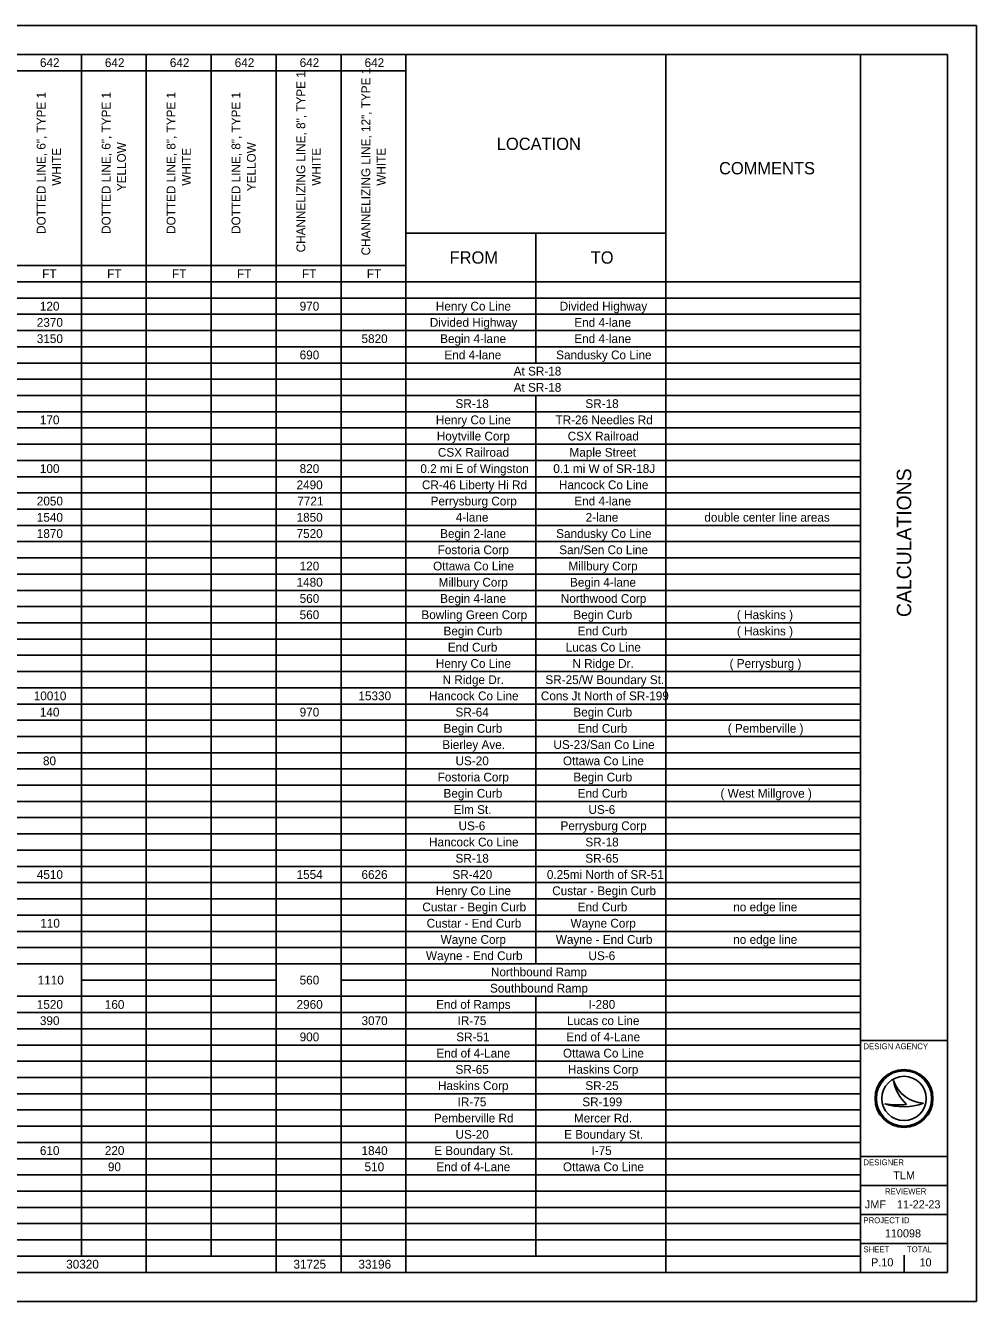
# Model space of a CAD drawing. Extents: x 0 to 34, y 0 to 22.
# Drawn here: x 17.6 to 34, y 0 to 22 of the extents above; entities that cross this region are included whole.
import ezdxf

# ---------------------------------------------------------------- set-up
doc = ezdxf.new("R2010")
doc.units = 0
for name, color, linetype in [('Default', 7, 'Continuous'), ('SH_Border', 7, 'Continuous'), ('SH_Cut_Line', 7, 'Continuous'), ('SH_Data', 7, 'Continuous')]:
    doc.layers.add(name, color=color, linetype=linetype)

msp = doc.modelspace()

# ---------------------------------------------------------------- linework, layer by layer
at = {"layer": 'Default'}
for p, q in [((1.5, 21.5), (32, 21.5)), ((18.562, 21.5), (18.562, 0.782)), ((19.681, 21.5), (19.681, 0.502)), ((20.801, 21.5), (20.801, 0.782)), ((21.921, 21.5), (21.921, 0.502)), ((23.041, 21.5), (23.041, 0.502)), ((24.161, 21.5), (24.161, 0.502)), ((28.64, 21.5), (28.64, 0.502)), ((32, 21.5), (32, 0.502)), ((8.483, 21.22), (24.161, 21.22)), ((24.161, 18.42), (28.64, 18.42)), ((26.401, 18.42), (26.401, 16.181)), ((8.483, 17.86), (24.161, 17.86)), ((1.5, 17.58), (32, 17.58)), ((2.505, 17.3), (32, 17.3)), ((2.505, 17.021), (32, 17.021)), ((2.505, 16.741), (32, 16.741)), ((2.505, 16.461), (32, 16.461)), ((2.505, 16.181), (32, 16.181)), ((2.505, 15.901), (32, 15.901)), ((2.505, 15.621), (32, 15.621)), ((26.401, 15.621), (26.401, 5.822)), ((2.505, 15.341), (32, 15.341)), ((2.505, 15.061), (32, 15.061)), ((2.505, 14.781), (32, 14.781)), ((2.505, 14.501), (32, 14.501)), ((2.505, 14.221), (32, 14.221)), ((2.505, 13.941), (32, 13.941)), ((2.505, 13.661), (32, 13.661)), ((2.505, 13.381), (32, 13.381)), ((2.505, 13.101), (32, 13.101)), ((2.505, 12.821), (32, 12.821)), ((2.505, 12.541), (32, 12.541)), ((2.505, 12.261), (32, 12.261)), ((2.505, 11.981), (32, 11.981)), ((2.505, 11.701), (32, 11.701)), ((2.505, 11.421), (32, 11.421)), ((2.505, 11.141), (32, 11.141)), ((2.505, 10.861), (32, 10.861)), ((2.505, 10.581), (32, 10.581)), ((2.505, 10.301), (32, 10.301)), ((2.505, 10.021), (32, 10.021)), ((2.505, 9.741), (32, 9.741)), ((2.505, 9.461), (32, 9.461)), ((2.505, 9.181), (32, 9.181)), ((2.505, 8.901), (32, 8.901)), ((2.505, 8.621), (32, 8.621)), ((2.505, 8.342), (32, 8.342)), ((2.505, 8.062), (32, 8.062)), ((2.505, 7.782), (32, 7.782)), ((2.505, 7.502), (32, 7.502)), ((2.505, 7.222), (32, 7.222)), ((2.505, 6.942), (32, 6.942)), ((2.505, 6.662), (32, 6.662)), ((2.505, 6.382), (32, 6.382)), ((2.505, 6.102), (32, 6.102)), ((2.505, 5.822), (32, 5.822)), ((18.562, 5.542), (21.921, 5.542)), ((23.041, 5.542), (32, 5.542)), ((2.505, 5.262), (32, 5.262)), ((26.401, 5.262), (26.401, 0.782)), ((2.505, 4.982), (32, 4.982)), ((2.505, 4.702), (32, 4.702)), ((2.505, 4.422), (32, 4.422)), ((2.505, 4.142), (32, 4.142)), ((2.505, 3.862), (32, 3.862)), ((2.505, 3.582), (32, 3.582)), ((2.505, 3.302), (32, 3.302)), ((2.505, 3.022), (32, 3.022)), ((2.505, 2.742), (32, 2.742)), ((2.505, 2.462), (32, 2.462)), ((1.5, 2.182), (32, 2.182)), ((1.5, 1.902), (32, 1.902)), ((1.5, 1.622), (32, 1.622)), ((1.5, 1.342), (32, 1.342)), ((1.5, 1.062), (32, 1.062)), ((1.5, 0.782), (32, 0.782)), ((1.5, 0.502), (32, 0.502))]:
    msp.add_line(p, q, dxfattribs=at)
at = {"layer": 'SH_Border'}
for p, q in [((32, 0.5), (32, 21.5)), ((32, 4.5), (33.5, 4.5)), ((32, 2.5), (33.5, 2.5)), ((32, 2), (33.5, 2)), ((32, 1.5), (33.5, 1.5)), ((32, 1), (33.5, 1))]:
    msp.add_line(p, q, dxfattribs=at)
msp.add_lwpolyline([(1.5, 21.5), (33.5, 21.5), (33.5, 0.5), (1.5, 0.5)], close=True, dxfattribs=at)
at = {"layer": 'SH_Cut_Line'}
msp.add_lwpolyline([(0, 0), (34, 0), (34, 22), (0, 22)], close=True, dxfattribs=at)
at = {"layer": 'SH_Data'}
for p, q in [((32.567, 3.81), (32.567, 3.81)), ((32.417, 3.41), (32.417, 3.41)), ((32.75, 3.5), (32.75, 3.5)), ((33.087, 3.419), (33.087, 3.419)), ((32.375, 0.675), (32.375, 0.675)), ((32.75, 0.5), (32.75, 0.8))]:
    msp.add_line(p, q, dxfattribs=at)
for radius in [0.5, 0.477, 0.477, 0.382]:
    msp.add_circle((32.75, 3.5), radius, dxfattribs=at)
for centre, radius, start, end in [((33.116, 3.998), 0.58, 198.9257, 198.9319), ((33.347, 3.97), 0.796, 191.6379, 191.6421), ((33.116, 3.998), 0.58, 198.9319, 267.1657), ((33.347, 3.97), 0.796, 191.6421, 226.0947), ((32.739, 4.37), 1.013, 251.4576, 290.0832), ((32.648, 4.654), 1.266, 259.4964, 259.4995), ((32.739, 4.37), 1.013, 251.4527, 251.4576), ((32.648, 4.654), 1.266, 259.4995, 276.6672)]:
    msp.add_arc(centre, radius, start, end, dxfattribs=at)

# ---------------------------------------------------------------- texts
at = {"layer": 'Default'}
for s, height, p in [('642', 0.1515, (17.848, 21.284)), ('642', 0.1515, (18.968, 21.284)), ('642', 0.1515, (20.088, 21.284)), ('642', 0.1515, (21.207, 21.284)), ('642', 0.1515, (22.327, 21.284)), ('642', 0.1515, (23.447, 21.284)), ('LOCATION', 0.2121, (25.727, 19.854)), ('COMMENTS', 0.2121, (29.56, 19.434)), ('FROM', 0.2121, (24.913, 17.894)), ('TO', 0.2121, (27.347, 17.894)), ('FT', 0.1515, (17.887, 17.645)), ('FT', 0.1515, (19.007, 17.645)), ('FT', 0.1515, (20.127, 17.645)), ('FT', 0.1515, (21.247, 17.645)), ('FT', 0.1515, (22.367, 17.645)), ('FT', 0.1515, (23.486, 17.645)), ('120', 0.1515, (17.847, 17.085)), ('970', 0.1515, (22.327, 17.085)), ('Henry Co Line', 0.15151, (24.676, 17.085)), ('Divided Highway', 0.15151, (26.812, 17.085)), ('2370', 0.1515, (17.794, 16.805)), ('Divided Highway', 0.15151, (24.572, 16.805)), ('End 4-lane', 0.1515, (27.064, 16.805)), ('3150', 0.1515, (17.794, 16.525)), ('5820', 0.1515, (23.394, 16.525)), ('Begin 4-lane', 0.15151, (24.75, 16.525)), ('End 4-lane', 0.1515, (27.064, 16.525)), ('690', 0.1515, (22.327, 16.245)), ('End 4-lane', 0.1515, (24.824, 16.245)), ('Sandusky Co Line', 0.15151, (26.751, 16.245)), ('At SR-18', 0.1515, (26.018, 15.965)), ('At SR-18', 0.1515, (26.018, 15.685)), ('SR-18', 0.1515, (25.015, 15.405)), ('SR-18', 0.1515, (27.255, 15.405)), ('170', 0.1515, (17.847, 15.125)), ('Henry Co Line', 0.15151, (24.676, 15.125)), ('TR-26 Needles Rd', 0.15151, (26.739, 15.125)), ('Hoytville Corp', 0.15151, (24.692, 14.845)), ('CSX Railroad', 0.15151, (26.95, 14.845)), ('CSX Railroad', 0.15151, (24.711, 14.565)), ('Maple Street', 0.15151, (26.981, 14.565)), ('100', 0.1515, (17.847, 14.285)), ('820', 0.1515, (22.327, 14.285)), ('0.2 mi E of Wingston', 0.15151, (24.409, 14.285)), ('0.1 mi W of SR-18J', 0.15151, (26.702, 14.285)), ('2490', 0.1515, (22.274, 14.005)), ('CR-46 Liberty Hi Rd', 0.15151, (24.436, 14.005)), ('Hancock Co Line', 0.15151, (26.799, 14.005)), ('2050', 0.1515, (17.794, 13.725)), ('7721', 0.1515, (22.287, 13.725)), ('Perrysburg Corp', 0.15151, (24.586, 13.725)), ('End 4-lane', 0.1515, (27.064, 13.725)), ('1540', 0.1515, (17.794, 13.445)), ('1850', 0.1515, (22.274, 13.445)), ('4-lane', 0.1515, (25.02, 13.445)), ('2-lane', 0.1515, (27.26, 13.445)), ('double center line areas', 0.15151, (29.307, 13.445)), ('1870', 0.1515, (17.794, 13.165)), ('7520', 0.1515, (22.274, 13.165)), ('Begin 2-lane', 0.15151, (24.75, 13.165)), ('Sandusky Co Line', 0.15151, (26.751, 13.165)), ('Fostoria Corp', 0.15151, (24.708, 12.885)), ('San/Sen Co Line', 0.15151, (26.804, 12.885)), ('Ottawa Co Line', 0.15151, (24.628, 12.605)), ('Millbury Corp', 0.15151, (26.963, 12.605)), ('120', 0.1515, (22.327, 12.605)), ('1480', 0.1515, (22.274, 12.325)), ('Millbury Corp', 0.15151, (24.724, 12.325)), ('Begin 4-lane', 0.15151, (26.99, 12.325)), ('560', 0.1515, (22.327, 12.045)), ('Begin 4-lane', 0.15151, (24.75, 12.045)), ('Northwood Corp', 0.15151, (26.831, 12.045)), ('560', 0.1515, (22.327, 11.765)), ('Bowling Green Corp', 0.15151, (24.427, 11.765)), ('Begin Curb', 0.1515, (27.048, 11.765)), ('( Haskins )', 0.15151, (29.868, 11.765)), ('Begin Curb', 0.1515, (24.808, 11.485)), ('End Curb', 0.1515, (27.122, 11.485)), ('( Haskins )', 0.15151, (29.868, 11.485)), ('End Curb', 0.1515, (24.882, 11.205)), ('Lucas Co Line', 0.15151, (26.916, 11.205)), ('Henry Co Line', 0.15151, (24.676, 10.925)), ('N Ridge Dr.', 0.15151, (27.031, 10.925)), ('( Perrysburg )', 0.15151, (29.742, 10.925)), ('N Ridge Dr.', 0.15151, (24.792, 10.645)), ('SR-25/W Boundary St.', 0.15151, (26.565, 10.645)), ('10010', 0.1515, (17.741, 10.366)), ('15330', 0.1515, (23.341, 10.366)), ('Hancock Co Line', 0.15151, (24.559, 10.366)), ('Cons Jt North of SR-199', 0.15151, (26.487, 10.366)), ('140', 0.1515, (17.847, 10.086)), ('970', 0.1515, (22.327, 10.086)), ('SR-64', 0.1515, (25.015, 10.086)), ('Begin Curb', 0.1515, (27.048, 10.086)), ('Begin Curb', 0.1515, (24.808, 9.806)), ('End Curb', 0.1515, (27.122, 9.806)), ('( Pemberville )', 0.15151, (29.71, 9.806)), ('Bierley Ave.', 0.15151, (24.788, 9.526)), ('US-23/San Co Line', 0.15151, (26.704, 9.526)), ('80', 0.1515, (17.9, 9.246)), ('US-20', 0.1515, (25.015, 9.246)), ('Ottawa Co Line', 0.15151, (26.868, 9.246)), ('Fostoria Corp', 0.15151, (24.708, 8.966)), ('Begin Curb', 0.1515, (27.048, 8.966)), ('Begin Curb', 0.1515, (24.808, 8.686)), ('End Curb', 0.1515, (27.122, 8.686)), ('( West Millgrove )', 0.15151, (29.585, 8.686)), ('Elm St.', 0.1515, (24.982, 8.406)), ('US-6', 0.1515, (27.308, 8.406)), ('US-6', 0.1515, (25.068, 8.126)), ('Perrysburg Corp', 0.15151, (26.826, 8.126)), ('Hancock Co Line', 0.15151, (24.559, 7.846)), ('SR-18', 0.1515, (27.255, 7.846)), ('SR-18', 0.1515, (25.015, 7.566)), ('SR-65', 0.1515, (27.254, 7.566)), ('4510', 0.1515, (17.794, 7.286)), ('1554', 0.1515, (22.274, 7.286)), ('6626', 0.1515, (23.393, 7.286)), ('SR-420', 0.1515, (24.962, 7.286)), ('0.25mi North of SR-51', 0.15151, (26.591, 7.286)), ('Henry Co Line', 0.15151, (24.676, 7.006)), ('Custar - Begin Curb', 0.15151, (26.683, 7.006)), ('Custar - Begin Curb', 0.15151, (24.443, 6.726)), ('End Curb', 0.1515, (27.122, 6.726)), ('no edge line', 0.15151, (29.805, 6.726)), ('Custar - End Curb', 0.15151, (24.517, 6.446)), ('110', 0.1515, (17.854, 6.446)), ('Wayne Corp', 0.1515, (26.999, 6.446)), ('Wayne Corp', 0.1515, (24.759, 6.166)), ('Wayne - End Curb', 0.15151, (26.745, 6.166)), ('no edge line', 0.15151, (29.805, 6.166)), ('Wayne - End Curb', 0.15151, (24.505, 5.886)), ('US-6', 0.1515, (27.308, 5.886)), ('Northbound Ramp', 0.15151, (25.626, 5.606)), ('1110', 0.1515, (17.809, 5.466)), ('560', 0.1515, (22.327, 5.466)), ('Southbound Ramp', 0.15151, (25.61, 5.326)), ('1520', 0.1515, (17.794, 5.046)), ('160', 0.1515, (18.967, 5.046)), ('2960', 0.1515, (22.274, 5.046)), ('End of Ramps', 0.15151, (24.681, 5.046)), ('I-280', 0.1515, (27.308, 5.046)), ('390', 0.1515, (17.847, 4.766)), ('3070', 0.1515, (23.394, 4.766)), ('IR-75', 0.1515, (25.052, 4.766)), ('Lucas co Line', 0.15151, (26.937, 4.766)), ('900', 0.1515, (22.327, 4.486)), ('SR-51', 0.1515, (25.028, 4.486)), ('End of 4-Lane', 0.15151, (26.926, 4.486)), ('End of 4-Lane', 0.15151, (24.686, 4.206)), ('Ottawa Co Line', 0.15151, (26.868, 4.206)), ('SR-65', 0.1515, (25.015, 3.926)), ('Haskins Corp', 0.15151, (26.953, 3.926)), ('Haskins Corp', 0.15151, (24.713, 3.646)), ('SR-25', 0.1515, (27.254, 3.646)), ('SR-199', 0.1515, (27.202, 3.366)), ('IR-75', 0.1515, (25.052, 3.366)), ('Pemberville Rd', 0.15151, (24.642, 3.086)), ('Mercer Rd.', 0.1515, (27.058, 3.086)), ('US-20', 0.1515, (25.015, 2.806)), ('E Boundary St.', 0.15151, (26.888, 2.806)), ('610', 0.1515, (17.847, 2.526)), ('220', 0.1515, (18.967, 2.526)), ('1840', 0.1515, (23.394, 2.526)), ('E Boundary St.', 0.15151, (24.648, 2.526)), ('I-75', 0.1515, (27.36, 2.526)), ('90', 0.1515, (19.02, 2.246)), ('510', 0.1515, (23.447, 2.246)), ('End of 4-Lane', 0.15151, (24.686, 2.246)), ('Ottawa Co Line', 0.15151, (26.868, 2.246)), ('30320', 0.1515, (18.301, 0.567)), ('31725', 0.1515, (22.22, 0.567)), ('33196', 0.1515, (23.341, 0.567))]:
    msp.add_text(s, height=height, dxfattribs=at).set_placement(p)
for s, height, p in [('CHANNELIZING LINE, 8", TYPE 1', 0.15151, (22.424, 18.089)), ('CHANNELIZING LINE, 12", TYPE 1', 0.15151, (23.544, 18.036)), ('DOTTED LINE, 6", TYPE 1', 0.15151, (17.945, 18.407)), ('DOTTED LINE, 6", TYPE 1', 0.15151, (19.065, 18.407)), ('DOTTED LINE, 8", TYPE 1', 0.15151, (20.185, 18.407)), ('DOTTED LINE, 8", TYPE 1', 0.15151, (21.304, 18.407)), ('WHITE', 0.1515, (18.21, 19.238)), ('YELLOW', 0.1515, (19.33, 19.144)), ('WHITE', 0.1515, (20.45, 19.238)), ('YELLOW', 0.1515, (21.57, 19.144)), ('WHITE', 0.1515, (22.689, 19.238)), ('WHITE', 0.1515, (23.809, 19.238))]:
    msp.add_text(s, height=height, rotation=90, dxfattribs=at).set_placement(p)
at = {"layer": 'SH_Data'}
msp.add_text('CALCULATIONS', height=0.25, rotation=90, dxfattribs=at).set_placement((32.875, 11.801))
for s, height, p in [('DESIGN AGENCY', 0.1, (32.05, 4.35)), ('DESIGNER', 0.1, (32.05, 2.35)), ('TLM', 0.14, (32.565, 2.105)), ('REVIEWER', 0.1, (32.422, 1.85)), ('JMF', 0.14, (32.075, 1.605)), ('11-22-23', 0.14, (32.629, 1.605)), ('PROJECT ID', 0.1, (32.05, 1.35)), ('110098', 0.14, (32.419, 1.105)), ('SHEET', 0.1, (32.05, 0.85)), ('TOTAL', 0.1, (32.8, 0.85)), ('P.10', 0.14, (32.182, 0.605)), ('10', 0.14, (33.017, 0.605))]:
    msp.add_text(s, height=height, dxfattribs=at).set_placement(p)

doc.saveas('drawing.dxf')
